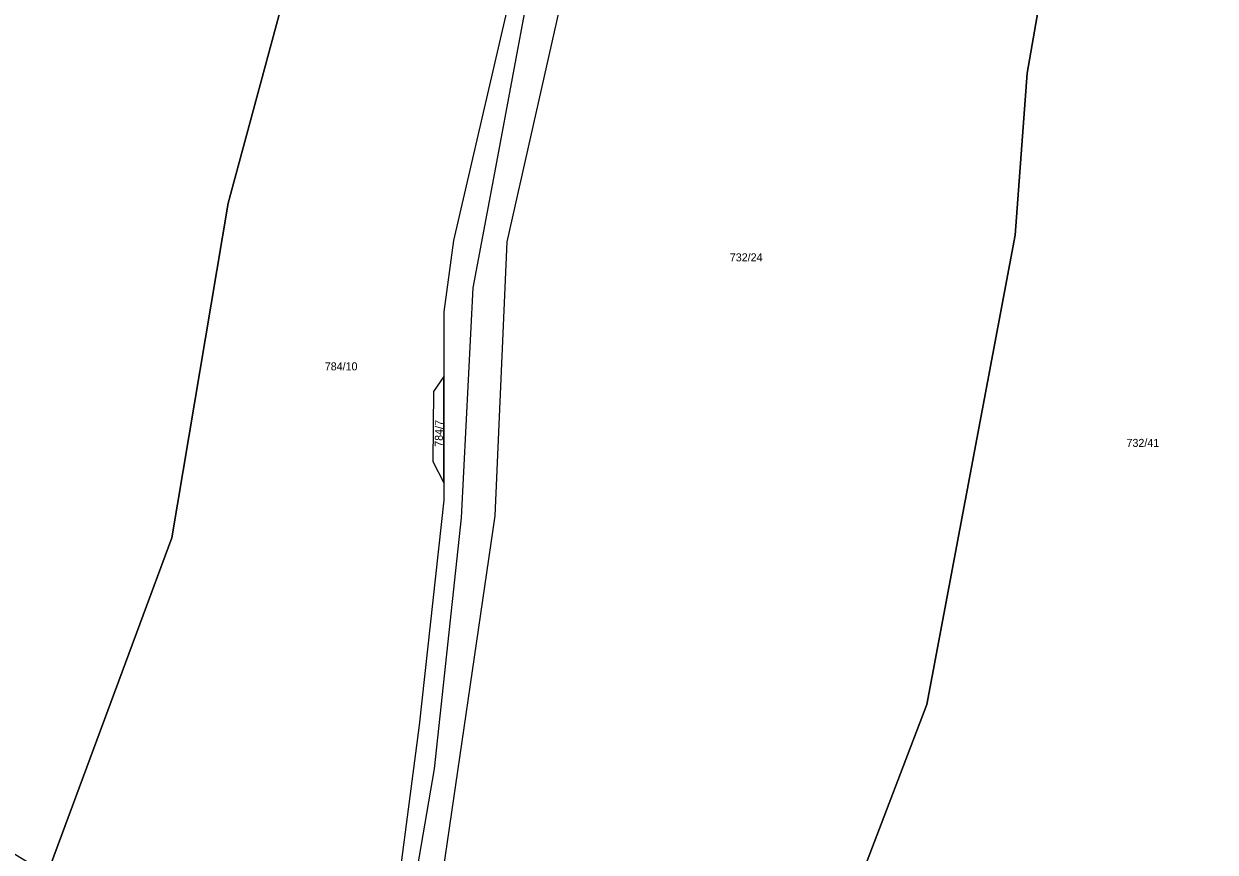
# Model space of a CAD drawing. Extents: x -588699 to -585793, y -1060280 to -1056731.
# Drawn here: x -587382.9 to -587129.7, y -1058273.1 to -1058097.1 of the extents above; entities that cross this region are included whole.
import ezdxf

# ---------------------------------------------------------------- set-up
doc = ezdxf.new("R2010")
doc.units = 0
doc.layers.add('Parcela nároku', color=7, linetype='Continuous')
doc.layers.add('Silnice', color=7, linetype='Continuous')

msp = doc.modelspace()

# ---------------------------------------------------------------- linework, layer by layer
at = {"layer": 'Parcela nároku'}
for points in [[(-587282.69, -1058201.62), (-587280.14, -1058143.43), (-587268.98, -1058093.77), (-587262.36, -1058075.98), (-587239.18, -1058041.88), (-587232.29, -1058031.28), (-587226.47, -1058025.59), (-587221.2, -1058018.45), (-587217.36, -1058010.52), (-587184.29, -1057977.65), (-587154.26, -1057974.05), (-587154.26, -1057976.54), (-587162.67, -1058067.38), (-587169.7, -1058107.61), (-587172.24, -1058142), (-587191.01, -1058241.74), (-587222.83, -1058325.23), (-587257.35, -1058309.41), (-587259.55, -1058300.98), (-587264.68, -1058293.6), (-587272.84, -1058298.75), (-587274.29, -1058301.65), (-587295.9, -1058291.75)], [(-587093.47, -1058042.85), (-587083.2, -1058085.63), (-587087.45, -1058131.23), (-587096.95, -1058176.54), (-587108.49, -1058212.36), (-587125.77, -1058278.15), (-587153.1, -1058357.53), (-587158, -1058368.22), (-587193.45, -1058428.69), (-587200.12, -1058424.25), (-587247.18, -1058391.8), (-587222.83, -1058325.23), (-587191.01, -1058241.74), (-587172.24, -1058142), (-587169.7, -1058107.61), (-587162.67, -1058067.38), (-587154.26, -1057976.54), (-587133.01, -1057983.57), (-587113.33, -1057983.29)], [(-587351.4, -1058206.3), (-587339.42, -1058135.2), (-587326.37, -1058086.73), (-587320.47, -1058029.95), (-587305.56, -1058030.56), (-587291.65, -1058024.66), (-587265.47, -1058015.84), (-587242.92, -1058025.69), (-587273.24, -1058072.71), (-587278.03, -1058084.71), (-587291.55, -1058143.14), (-587293.59, -1058158.32), (-587293.6, -1058172.06), (-587295.78, -1058175.26), (-587295.94, -1058190.13), (-587293.6, -1058194.6), (-587293.61, -1058198.3), (-587298.84, -1058246.13), (-587305.16, -1058294.29), (-587309.56, -1058312.62), (-587312.09, -1058322.87), (-587377.92, -1058277.75)], [(-587345.44, -1058028.92), (-587320.47, -1058029.95), (-587326.37, -1058086.73), (-587339.42, -1058135.2), (-587351.4, -1058206.3), (-587377.92, -1058277.75), (-587409.09, -1058258.83), (-587438.17, -1058230.02), (-587444.54, -1058218.88), (-587478.83, -1058188.89), (-587488.81, -1058140.74), (-587488.94, -1058128.88), (-587485.87, -1058116.62), (-587469.24, -1058080.38), (-587460.27, -1058069.38), (-587445.31, -1058054.69), (-587393.66, -1058044.61), (-587379.52, -1058038.97), (-587353.28, -1058031.95)], [(-587295.78, -1058175.26), (-587295.94, -1058190.13), (-587293.6, -1058194.6), (-587293.6, -1058172.06)]]:
    msp.add_lwpolyline(points, close=True, dxfattribs=at)
for points in [[(-587278.03, -1058084.71), (-587291.55, -1058143.14), (-587293.59, -1058158.32), (-587293.6, -1058172.06), (-587293.6, -1058194.6), (-587293.61, -1058198.3), (-587298.84, -1058246.13), (-587305.16, -1058294.29)], [(-587295.9, -1058291.75), (-587282.69, -1058201.62), (-587280.14, -1058143.43), (-587268.98, -1058093.77)]]:
    msp.add_lwpolyline(points, dxfattribs=at)
at = {"layer": 'Silnice'}
msp.add_lwpolyline([(-587345.08, -1058454.6), (-587343.22, -1058435.34), (-587340.2, -1058422.73), (-587333.83, -1058405.7), (-587323.03, -1058372.85), (-587310.8, -1058335.66), (-587304.81, -1058309.03), (-587295.59, -1058255.42), (-587289.86, -1058202.05), (-587287.36, -1058153.18), (-587282.38, -1058126.49), (-587275.7, -1058090.71), (-587265.43, -1058067.39), (-587238.5, -1058030.49), (-587225.54, -1058012.73), (-587221.55, -1057994.83), (-587230.27, -1057964.15), (-587260.19, -1057868.4), (-587294.78, -1057755.78)], dxfattribs=at)

# ---------------------------------------------------------------- texts
at = {"layer": 'Parcela nároku'}
for s, p in [('732/24', (-587232.85, -1058147.57)), ('784/10', (-587318.91, -1058170.74)), ('732/41', (-587148.56, -1058187))]:
    msp.add_text(s, height=1.7, dxfattribs=at).set_placement(p)
msp.add_text('784/7', height=1.7, rotation=88.5434, dxfattribs=at).set_placement((-587293.87, -1058187))

doc.saveas('drawing.dxf')
